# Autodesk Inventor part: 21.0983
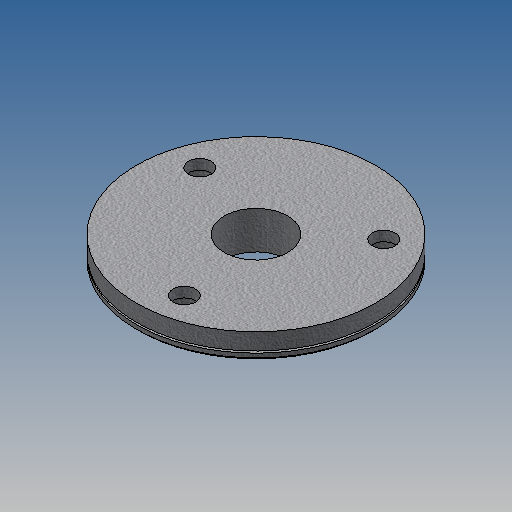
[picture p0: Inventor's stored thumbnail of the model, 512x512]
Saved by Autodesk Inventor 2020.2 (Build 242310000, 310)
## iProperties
Created: 2018-02
Part Number: 21.0983
Material: AL 6061-T6
Document SubType Name: Modeling
Designer: Admin
Density: 2.7 g/cm^3
Mass: 171.542 g
Surface Area: 184.37 cm^2
Volume: 63.5341 cm^3
Description: END DISK FOR CYLINDER PROFILE 90
Stock Number: 21.0983 END DISK FOR CYLINDER PROFILE 90
Appearance: Aluminum Cast
Translation Standard: STEP AP203
FileName: Trommel.stp
PreProcessor: Mechanical Desktop 2011
PostProcessor: Build: 160, Release: 2012 RTM - Date: Tue 03/01/2011
Sent Units: inch
Uncertainty: 1.0000000000000002e-06
Author: Admin
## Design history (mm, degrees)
feature "Base5"
sketch "Sketch2"
  geometry: L1 (-9, 47.5)-(-9, -47.5) reference; L2 (0, 47.5)-(0, -47.5) reference; L3 (-7.375, -47.5)-(-7, -46); L4 (-7, -46)-(-6.625, -47.5); L5 (-6.625, -47.5)-(-7.375, -47.5); L6 (0, -47.5)-(-9, -47.5) reference; L7 (-10, 46.5)-(-10, -46.5) reference; L8 (-18, 0)-(3, 0) reference; 1 further point
  constraints: 6 end point, 1 collinear, 1 point on line
  dimensions: "d0" = 1.5 distance from line of L3.end L6; "d1" = 0.375 horizontal distance of L3.start L3.end (= 0.25 x d0); "d2" = 0.375 horizontal distance of L3.end L4.end (= d1); "d3" = 3 distance from line of L3.end L7
revolve "Revolution1" sketch "Sketch2" stored, may be unused: angle "d4" = 90 deg
node "F35F"
node "F28B"
node "Projected Loop1"
